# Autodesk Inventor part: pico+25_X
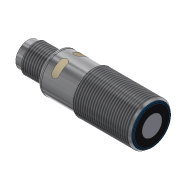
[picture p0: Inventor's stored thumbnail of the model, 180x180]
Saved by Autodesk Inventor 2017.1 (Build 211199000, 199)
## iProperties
Shininess: 20.0
Length Units: 11269
Angle Units: 11279
Time Units: 11290
Mass Units: 11283
Length Display Precision: 2
Angle Display Precision: 2
Part Number: pico+25_X
Material: Nichtrostender Stahl - 440C
Document SubType Name: Modellieren
Description: Ipc-25 /CXX/M18
Checked By: Alves
Created: 2005-08
Designer: Ohle
Manufacturer: Standard
Standards Organization: Custom
Appearance: Aluminium - poliert
Density: 0.0
Volumn: 0.0
Area: 0.0
PropertySet Name: Model Information
Control State: 0
Master: False
Checked Out: False
BESTELLNUMMER: Ipc-25 /CXX/M18
ME: ST
Title: Ipc Sensoren
Author: Ohle
Comments: keine Bemerkung
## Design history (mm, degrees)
sketch "Skizze10"
  geometry: L1 (-42.478, 0)-(2.095, 0); L2 (-38.478, 6.5)-(-38.478, 7.25); L3 (-45.9, 8)-(-45.9, 8); L4 (-22.728, 9)-(0.772, 9); L5 (2.085, 7.4)-(2.085, 4.25); L6 (2.085, 4.25)-(2.095, 4.25); L7 (2.095, 4.25)-(2.095, 0); L8 (2.095, 0)-(-82, 0); L9 (1.522, 8.25)-(1.522, 8.25); L10 (-23.478, 8.25)-(-22.728, 9); L11 (1.522, 8.25)-(0.772, 9); L12 (-49.978, 6)-(-38.978, 6); L13 (-36.878, 8.25)-(-23.478, 8.25); L14 (-50.478, 4.5)-(-42.478, 4.5); L15 (-42.478, 0)-(-42.478, 4.5); L16 (-36.978, 8.25)-(-37.478, 8.25); L17 (1.522, 8.25)-(1.522, 8.25); L18 (-38.978, 6)-(-38.478, 6.5); L19 (-50.478, 5.5)-(-50.478, 4.5); L20 (-50.478, 5.5)-(-49.978, 6); L21 (-36.978, 8.25)-(-36.978, 8.15); L22 (-36.978, 8.15)-(-36.878, 8.15); L23 (-36.878, 8.15)-(-36.878, 8.25); L24 (1.522, 8.25)-(1.595, 8.25); L25 (1.595, 8.25)-(1.795, 8.25); L26 (2.095, 7.95)-(2.095, 7.4); L27 (2.095, 7.4)-(2.085, 7.4); A1 r 1 centre (-37.478, 7.25) between (-37.478, 8.25) and (-38.478, 7.25); A2 r 0.3 centre (1.795, 7.95) between (2.095, 7.95) and (1.795, 8.25); 4 further points
  constraints: 54 end point, 8 point on line, 7 perpendicular, 5 parallel, 4 point on circle, 4 tangent, 2 centre point, 2 horizontal, 1 collinear
  dimensions: "d136" = 4.25 distance of L6.end L1.end; "d138" = 9 distance between parallel lines of L4 L8; "d171" = 4.5 distance between parallel lines of L14 L1; "d250" = 0.75 distance from line of L11.start L4; "d256" = 45 deg angle of L4 L10; "d257" = 8.25 distance between parallel lines of L8 L13; "d263" = 8.25 distance between parallel lines of L8 L16; "d266" = 12 distance from line of L2 L19.start; "d269" = 6 distance between parallel lines of L8 L12; "d289" = 135 deg angle of L11 L4; "d290" = 0.5 horizontal distance of L12.end L2.start; "d291" = 45 deg angle of L18 L12 (derived); "d293" = 0.5 horizontal distance of L19.start L12.start; "d294" = 45 deg angle of L20 L12 (derived); "d295" = 8 distance of L14.start L14.end; "d296" = 1.5 distance of L16.start point (-38.478, 8.25); "d297" = 0.1 distance of L21.end L22.end; "d298" = 8.15 distance between parallel lines of L22 L1; "d299" = 15 distance from line of L10.start L2; "d300" = 1 radius of A1; "d331" = 0.01 distance between parallel lines of L5 L7; "d334" = 0.5 distance of L24.end point (2.095, 8.25); "d335" = 0.3 radius of A2; "d337" = 25 distance of L10.start L11.start; "d338" = 0.01 distance between parallel lines of L26 L5; "d339" = 7.4 distance between parallel lines of L8 L27
revolve "Grundkörper pico+" sketch "Skizze10" stored, may be unused: angle "d168" = 90 deg
feature "Gewinde M12" dims "d174" = 10, "d175" = 0
feature "Gewinde M 18" dims "d179" = 10, "d180" = 0
workplane "Arbeitsebene1"
workplane "Arbeitsebene2"
sketch "Skizze13"
  geometry: L1 (-3.409, -3.409)-(3.61, 3.61); L2 (-3.439, 3.439)-(4.105, -4.105); L3 (-12.6, 0)-(12.6, 0) reference; C1 r 0.5 at (2.121, -2.121); C2 r 0.5 at (2.121, 2.121); C3 r 0.5 at (-2.121, 2.121); C4 r 0.5 at (-2.121, -2.121); C5 r 4.5 at (0, 0) reference; C6 r 0.5 at (0, 0); A1 r 3 centre (0, 0) between (-2.121, 2.121) and (2.121, 2.121); 2 further points
  constraints: 6 centre point, 6 point on line, 4 coincident, 4 end point, 4 equal radius, 4 point on circle, 1 horizontal alignment, 1 perpendicular
  dimensions: "d208" = 1 diameter of C3; "d209" = 6 diameter of A1
extrude "Pole" join sketch "Skizze13" distance "d212" = 7; taper "d213" = 0 deg
fillet "Rundung Pole" dims "d214" = 0.5
sketch "Skizze14"
  geometry: C1 r 0.5 at (0, -4.5); A1 r 4.5 centre (0, 0) between (4.435, -0.762) and (4.435, 0.762); A2 r 4.5 centre (0, 0) between (0, 4.5) and (0.499, 4.472) reference; A3 r 0.5 centre (0, 4.5) between (-0.499, 4.472) and (0.499, 4.472); 3 further points
  constraints: 9 point on circle, 3 centre point, 3 coincident, 1 horizontal alignment, 1 vertical alignment
  dimensions: "d215" = 9 diameter of A1; "d280" = 1 diameter of A3; "d330" = 1 diameter of C1
extrude "Verdrehsicherung" join sketch "Skizze14" distance "d217" = 7; taper "d218" = 0 deg
sketch "Skizze18"
  geometry: C1 r 7.25 at (0, 0) reference; C2 r 1 at (-8.15, 0)
  constraints: 1 centre point, 1 horizontal alignment
  dimensions: "d328" = 2 diameter of C2; "d329" = 8.15 distance of C1.centre C2.centre
extrude "Bohrung Ausrichtung" cut sketch "Skizze18" distance "d316" = 0.75; taper "d317" = 0 deg
workplane "Arbeitsebene4"
sketch "Skizze19"
  geometry: L1 (-38.478, 0)-(-30.18, 0); L2 (-34.178, -7.5)-(-34.178, -3); L3 (-31.178, -7.5)-(-31.178, -3); L4 (-31.178, 3)-(-31.178, 7.5); L5 (-34.178, 3)-(-34.178, 7.5); A1 r 1.5 centre (-32.678, 3) between (-31.178, 3) and (-34.178, 3); A2 r 1.5 centre (-32.678, -3) between (-34.178, -3) and (-31.178, -3); A3 r 1.5 centre (-32.678, 7.5) between (-31.178, 7.5) and (-34.178, 7.5); A4 r 1.5 centre (-32.678, -7.5) between (-34.178, -7.5) and (-31.178, -7.5); 4 further points; 1 other entity
  constraints: 10 end point, 8 point on circle, 8 tangent, 4 centre point, 3 equal radius, 2 vertical alignment, 1 horizontal, 2 other
  dimensions: "d319" = 3 diameter of A2; "d320" = 6 distance of A2.centre A1.centre; "d321" = 4.5 distance of A1.centre A3.centre; "d322" = 4.5 distance of A4.centre A2.centre; "d323" = 3 distance from line of A2.centre L1; "d324" = 5.8 dimension on A1.centre; "d325" = 5.8 dimension on A2.centre
feature "Prägen LED-Fenster" sketch "Skizze19" dims "d326" = 0.01, "d327" = 0
sketch "Skizze21"
  geometry: C1 r 5.5 at (0, 0); C2 r 4.5 at (0, 0); C3 r 4.15 at (0, 0); C4 r 5.25 at (0, 0); 3 further points
  constraints: 4 centre point
  dimensions: "d340" = 8.3 diameter of C3; "d341" = 10.5 diameter of C4
extrude "Extrusion5" join sketch "Skizze21" stored distance "d342" = 1; taper "d343" = 0 deg
sketch "Skizze22"
  geometry: C1 r 5.25 at (0, 0) reference; C2 r 9.924 at (0, 0); 1 further point
  constraints: 1 centre point
extrude "Extrusion6" cut sketch "Skizze22" distance "d344" = 2.6; taper "d345" = 0 deg
chamfer "Fase2" distance "d346" = 0.75; stored, may be unused: second distance "d347" = 2, angle "d348" = 30 deg
node "Volumenkörper1"
node "Volumenkörper"
node "Oberflächenkörper"
other parameters: "d10" = 14, "d73" = -35, "d130" = 0.2, "d207" = -95.5, "d318" = 8.25
